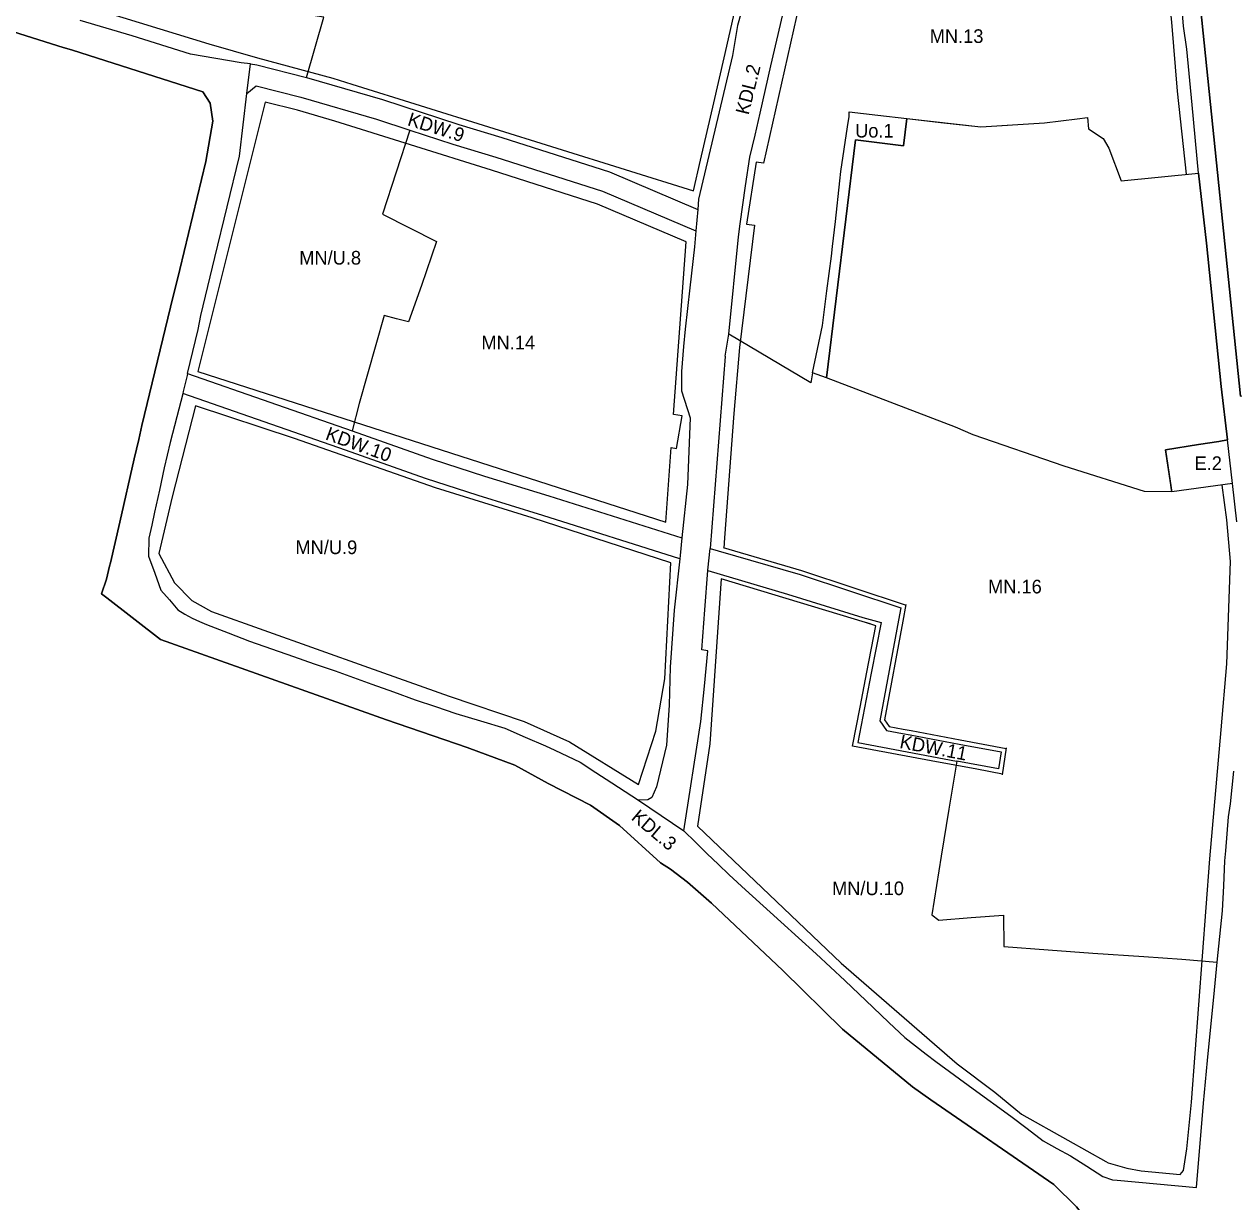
# Model space of a CAD drawing. Extents: x 7423274 to 7424514, y 5542390 to 5544261.
# Drawn here: x 7423885.8 to 7424240.7, y 5543020.6 to 5543366 of the extents above; entities that cross this region are included whole.
import ezdxf

# ---------------------------------------------------------------- set-up
doc = ezdxf.new("R2010")
doc.units = 0
for name, color, linetype in [('granica obszaru objętego planem', 7, 'Continuous'), ('LIN_Granica Planu', 7, 'Continuous'), ('linie rozgraniczające tereny o różnym przeznaczeniu lub różnych zasadach zagospodarowania', 7, 'Continuous'), ('nieprzekraczalna linia zabudowy', 7, 'Continuous'), ('oznaczenia terenów', 7, 'Continuous'), ('tereny dka ktorych obowiazuje_355', 7, 'Continuous')]:
    doc.layers.add(name, color=color, linetype=linetype)

msp = doc.modelspace()

# ---------------------------------------------------------------- linework, layer by layer
at = {"layer": 'granica obszaru objętego planem'}
for p, q in [((7424228.51, 5543394.73), (7424242.62, 5543256.86)), ((7423897.3, 5543359.16), (7423878.95, 5543364.84)), ((7423928.79, 5543282.97), (7423931.47, 5543294.03)), ((7423911.15, 5543208.03), (7423913.87, 5543219.9)), ((7423910, 5543203.23), (7423910.81, 5543207.01)), ((7423910.81, 5543207.01), (7423911.15, 5543208.03)), ((7423908.54, 5543198.88), (7423910, 5543203.23)), ((7423910.05, 5543197.7), (7423908.54, 5543198.88)), ((7423925.77, 5543185.5), (7423910.05, 5543197.7)), ((7423992.07, 5543161.97), (7423925.77, 5543185.5)), ((7424015.82, 5543153.8), (7423992.07, 5543161.97)), ((7424072.5, 5543120.05), (7424060.48, 5543130.94)), ((7424075.4, 5543118.16), (7424072.5, 5543120.05)), ((7424080.4, 5543114.34), (7424075.4, 5543118.16)), ((7424125.89, 5543071.27), (7424108.39, 5543088.46)), ((7424146.47, 5543054.35), (7424125.89, 5543071.27)), ((7424151.82, 5543050.55), (7424146.47, 5543054.35)), ((7424187.91, 5543025.65), (7424151.82, 5543050.55))]:
    msp.add_line(p, q, dxfattribs=at)
for points in [[(7423899.98, 5543358.31), (7423898.37, 5543358.83), (7423897.3, 5543359.16)], [(7423931.47, 5543294.03), (7423939.15, 5543325.65), (7423941.13, 5543337.55), (7423940.41, 5543342.77), (7423938.19, 5543346.07), (7423899.98, 5543358.31)], [(7423919.43, 5543244.17), (7423920.36, 5543248.23), (7423928.79, 5543282.97)], [(7423913.87, 5543219.9), (7423918.12, 5543238.46), (7423919.43, 5543244.17)], [(7424039.53, 5543143.25), (7424029.77, 5543148.7), (7424015.82, 5543153.8)], [(7424060.48, 5543130.94), (7424051.94, 5543136.91), (7424039.53, 5543143.25)], [(7424108.39, 5543088.46), (7424087.42, 5543108.21), (7424080.4, 5543114.34)], [(7424206.38, 5543004.09), (7424194.57, 5543019.14), (7424187.91, 5543025.65)]]:
    msp.add_lwpolyline(points, dxfattribs=at)
at = {"layer": 'LIN_Granica Planu'}
for p, q in [((7424242.62, 5543256.86), (7424228.51, 5543394.73)), ((7423878.95, 5543364.84), (7423897.3, 5543359.16)), ((7423931.47, 5543294.03), (7423928.79, 5543282.97)), ((7423913.87, 5543219.9), (7423911.15, 5543208.03)), ((7423910.81, 5543207.01), (7423910, 5543203.23)), ((7423911.15, 5543208.03), (7423910.81, 5543207.01)), ((7423910, 5543203.23), (7423908.54, 5543198.88)), ((7423908.54, 5543198.88), (7423910.05, 5543197.7)), ((7423910.05, 5543197.7), (7423925.77, 5543185.5)), ((7423925.77, 5543185.5), (7423992.07, 5543161.97)), ((7423992.07, 5543161.97), (7424015.82, 5543153.8)), ((7424060.48, 5543130.94), (7424072.5, 5543120.05)), ((7424072.5, 5543120.05), (7424075.4, 5543118.16)), ((7424075.4, 5543118.16), (7424080.4, 5543114.34)), ((7424108.39, 5543088.46), (7424125.89, 5543071.27)), ((7424125.89, 5543071.27), (7424146.47, 5543054.35)), ((7424146.47, 5543054.35), (7424151.82, 5543050.55)), ((7424151.82, 5543050.55), (7424187.91, 5543025.65))]:
    msp.add_line(p, q, dxfattribs=at)
for points in [[(7423897.3, 5543359.16), (7423898.37, 5543358.83), (7423899.98, 5543358.31)], [(7423899.98, 5543358.31), (7423938.19, 5543346.07), (7423940.41, 5543342.77), (7423941.13, 5543337.55), (7423939.15, 5543325.65), (7423931.47, 5543294.03)], [(7424159.02, 5543247.82), (7424133.19, 5543257.64), (7424121.2, 5543262.2), (7424129.68, 5543332.07), (7424143.76, 5543330.24), (7424144.72, 5543338.31), (7424166.46, 5543335.81), (7424185.12, 5543337.07), (7424194.74, 5543338.24), (7424197.78, 5543338.6), (7424198.07, 5543335.23), (7424202.37, 5543332.42), (7424204.03, 5543329.61), (7424207.65, 5543320), (7424230.35, 5543322.31), (7424232.64, 5543301.72), (7424237.01, 5543259.68), (7424238.8, 5543244.06), (7424236.28, 5543243.6), (7424230.36, 5543242.65), (7424220.63, 5543241.1), (7424222.35, 5543229.95), (7424222.51, 5543228.86), (7424214.52, 5543228.92), (7424190.92, 5543236.36), (7424164.25, 5543245.56), (7424159.02, 5543247.82)], [(7423928.79, 5543282.97), (7423920.36, 5543248.23), (7423919.43, 5543244.17)], [(7423919.43, 5543244.17), (7423918.12, 5543238.46), (7423913.87, 5543219.9)], [(7424015.82, 5543153.8), (7424029.77, 5543148.7), (7424039.53, 5543143.25)], [(7424039.53, 5543143.25), (7424051.94, 5543136.91), (7424060.48, 5543130.94)], [(7424080.4, 5543114.34), (7424087.42, 5543108.21), (7424108.39, 5543088.46)], [(7424187.91, 5543025.65), (7424194.57, 5543019.14), (7424206.38, 5543004.09)]]:
    msp.add_lwpolyline(points, dxfattribs=at)
at = {"layer": 'linie rozgraniczające tereny o różnym przeznaczeniu lub różnych zasadach zagospodarowania'}
msp.add_line((7424130.38, 5543155.27), (7424130.38, 5543155.27), dxfattribs=at)
for points in [[(7424129.39, 5544001.9), (7424129.8, 5543999.91), (7424131.7, 5543990.87), (7424133.97, 5543980.01), (7424148.11, 5543912.49), (7424163.08, 5543838.56), (7424169.46, 5543807.01), (7424175.57, 5543776.81), (7424186.15, 5543728.82), (7424192.74, 5543698.89), (7424202.07, 5543636.25), (7424204.36, 5543612.15), (7424228.15, 5543398.17), (7424228.51, 5543394.73), (7424242.62, 5543256.86), (7424248.04, 5543257.08)], [(7424092.5, 5543275.06), (7424095.41, 5543303.55), (7424095.87, 5543307.37), (7424097.46, 5543318.57), (7424098.68, 5543326.94), (7424100.22, 5543333.4), (7424101.76, 5543339.86), (7424103.33, 5543346.79), (7424104.9, 5543353.71), (7424110.13, 5543376.43), (7424113.79, 5543392.37), (7424117.5, 5543408.62), (7424119.5, 5543417.47), (7424120.06, 5543424.28), (7424124.99, 5543426.4)], [(7424230.35, 5543322.31), (7424228.43, 5543342.33), (7424226.86, 5543358.67), (7424225.94, 5543365.33), (7424224.84, 5543378.57), (7424223.86, 5543388.69), (7424223.21, 5543394.21)], [(7423968.62, 5543350.36), (7423973.77, 5543367.98), (7423958.39, 5543370.37), (7423960.3, 5543381.21), (7423951.96, 5543383.71), (7423943.62, 5543386.21), (7423943.52, 5543385.47), (7423934.92, 5543388.04), (7423926.32, 5543390.6), (7423925.03, 5543386.46), (7423923.73, 5543382.33), (7423914.57, 5543383.96), (7423905.4, 5543385.58)], [(7424096.17, 5543369.34), (7424095.06, 5543365.57), (7424093.62, 5543356.78), (7424089.74, 5543340.3), (7424083.68, 5543314.62), (7424083.42, 5543311.6)], [(7423952.21, 5543354.3), (7423949.45, 5543354.66), (7423934.63, 5543357.19), (7423917.53, 5543362.55), (7423902.29, 5543367.06)], [(7424194.57, 5543019.14), (7424187.91, 5543025.65), (7424151.82, 5543050.55), (7424146.47, 5543054.35), (7424125.89, 5543071.27), (7424108.39, 5543088.46), (7424087.42, 5543108.21), (7424080.4, 5543114.34), (7424075.4, 5543118.16), (7424072.5, 5543120.05), (7424060.48, 5543130.94), (7424051.94, 5543136.91), (7424039.53, 5543143.25), (7424029.77, 5543148.7), (7424015.82, 5543153.8), (7423992.07, 5543161.97), (7423925.77, 5543185.5), (7423910.05, 5543197.7), (7423908.54, 5543198.88), (7423910, 5543203.23), (7423910.81, 5543207.01), (7423911.15, 5543208.03), (7423913.87, 5543219.9), (7423918.12, 5543238.46), (7423919.43, 5543244.17), (7423920.36, 5543248.23), (7423928.79, 5543282.97), (7423931.47, 5543294.03), (7423939.15, 5543325.65), (7423941.13, 5543337.55), (7423940.41, 5543342.77), (7423938.19, 5543346.07), (7423899.98, 5543358.31), (7423898.37, 5543358.83), (7423897.3, 5543359.16), (7423878.95, 5543364.84)], [(7423951.18, 5543345.64), (7423952.21, 5543354.3)], [(7423952.21, 5543354.3), (7423954.1, 5543354.05), (7423968.62, 5543350.36)], [(7423951.18, 5543345.64), (7423953.92, 5543347.91), (7423967.03, 5543344.57), (7423989.14, 5543338.1), (7423998.99, 5543334.88)], [(7423968.62, 5543350.36), (7423990.91, 5543343.83), (7424013.35, 5543336.51), (7424025.92, 5543332.71), (7424057.54, 5543322.61), (7424083.42, 5543311.6)], [(7423933.76, 5543263.48), (7423936.86, 5543276.41), (7423937.65, 5543280.51), (7423941.79, 5543297.58), (7423949, 5543327.23), (7423951.18, 5543345.64)], [(7424117.13, 5543263.74), (7424120.04, 5543277.56), (7424121.33, 5543287.73), (7424122.62, 5543297.9), (7424122.98, 5543300.77), (7424123.83, 5543308.11), (7424125.15, 5543320), (7424125.42, 5543322.72), (7424126.41, 5543329.28), (7424127.39, 5543335.83), (7424127.84, 5543338.85), (7424127.81, 5543340.26), (7424136.27, 5543339.29), (7424144.72, 5543338.31), (7424155.59, 5543337.06), (7424166.46, 5543335.81), (7424175.79, 5543336.44), (7424185.12, 5543337.07), (7424189.93, 5543337.66), (7424194.74, 5543338.24), (7424197.78, 5543338.6), (7424198.07, 5543335.23), (7424202.37, 5543332.42), (7424204.03, 5543329.61), (7424207.65, 5543320), (7424230.35, 5543322.31)], [(7424144.72, 5543338.31), (7424143.76, 5543330.24), (7424129.68, 5543332.07), (7424121.2, 5543262.2)], [(7423998.99, 5543334.88), (7423994.96, 5543322.56), (7423990.91, 5543310.22), (7423998.87, 5543306.21), (7424006.82, 5543302.21), (7424002.34, 5543289.37), (7423998.59, 5543278.63), (7423995.01, 5543279.57), (7423991.43, 5543280.51), (7423988.99, 5543271.92), (7423986.54, 5543263.34), (7423984.09, 5543254.75), (7423982.08, 5543246.68)], [(7423998.99, 5543334.88), (7424011.55, 5543330.78), (7424024.14, 5543326.98), (7424055.45, 5543316.98), (7424082.86, 5543305.31)], [(7424238.8, 5543244.06), (7424237.01, 5543259.68), (7424232.64, 5543301.72), (7424230.35, 5543322.31)], [(7424083.42, 5543311.6), (7424082.86, 5543305.31)], [(7424082.86, 5543305.31), (7424082.46, 5543300.69), (7424081.08, 5543288.61), (7424079.69, 5543276.53), (7424079.26, 5543271.4), (7424078.63, 5543264.1), (7424078.68, 5543258.46), (7424078.68, 5543258.41), (7424081.22, 5543250.56), (7424080.42, 5543230.98), (7424078.79, 5543215.31)], [(7424091.5, 5543268.63), (7424092.5, 5543275.06)], [(7424117.13, 5543263.74), (7424116.6, 5543260.73), (7424092.5, 5543275.06)], [(7424091.49, 5543268.48), (7424087.03, 5543212.2)], [(7424091.5, 5543268.63), (7424091.49, 5543268.48)], [(7423933.76, 5543263.48), (7423933.62, 5543262.88), (7423933.05, 5543260.55), (7423932.48, 5543258.22), (7423932.33, 5543257.62)], [(7423933.76, 5543263.48), (7423982.08, 5543246.68)], [(7424222.51, 5543228.86), (7424214.52, 5543228.92), (7424190.92, 5543236.36), (7424164.25, 5543245.56), (7424159.02, 5543247.82), (7424133.19, 5543257.64), (7424121.2, 5543262.2), (7424117.13, 5543263.74)], [(7423932.32, 5543257.58), (7423930.58, 5543250.76), (7423928.69, 5543243.3), (7423926.88, 5543235.89), (7423925.48, 5543229.35), (7423924.07, 5543222.81), (7423923.23, 5543219.02), (7423922.39, 5543215.23), (7423922.33, 5543209.95), (7423924.14, 5543204.98), (7423925.95, 5543200.01), (7423928.42, 5543197.11), (7423930.9, 5543194.21), (7423933, 5543192.98), (7423935.09, 5543191.74), (7423937.22, 5543190.81), (7423939.35, 5543189.88), (7423945.63, 5543187.46), (7423951.91, 5543185.03), (7423958.39, 5543182.78), (7423964.87, 5543180.52), (7423970.94, 5543178.41), (7423977.01, 5543176.3), (7423982.39, 5543174.37), (7423987.77, 5543172.43), (7423994.15, 5543170.14), (7424000.52, 5543167.85), (7424006.49, 5543165.84), (7424012.45, 5543163.83), (7424019.66, 5543161.67), (7424026.86, 5543159.51), (7424032.82, 5543156.91), (7424038.77, 5543154.31), (7424041.49, 5543153.03), (7424045.19, 5543151.29), (7424048.89, 5543149.55), (7424053.57, 5543146.51), (7424058.24, 5543143.48), (7424062.15, 5543140.95), (7424066.06, 5543138.41)], [(7423932.33, 5543257.62), (7423932.32, 5543257.58)], [(7423932.33, 5543257.62), (7423932.32, 5543257.58)], [(7424078.16, 5543209.21), (7424037.99, 5543221.88), (7424019.03, 5543227.72), (7424003.55, 5543232.72), (7423980.09, 5543241.02), (7423932.33, 5543257.62)], [(7423932.33, 5543257.62), (7423932.33, 5543257.62)], [(7423982.08, 5543246.68), (7424005.47, 5543238.4), (7424020.83, 5543233.45), (7424039.77, 5543227.61), (7424078.79, 5543215.31)], [(7424222.51, 5543228.86), (7424222.35, 5543229.95), (7424222.21, 5543230.86), (7424220.63, 5543241.1), (7424230.36, 5543242.65), (7424236.28, 5543243.6), (7424238.8, 5543244.06)], [(7424240.28, 5543231.21), (7424238.8, 5543244.06)], [(7424240.28, 5543231.21), (7424222.51, 5543228.86)], [(7424241.58, 5543219.98), (7424240.28, 5543231.21)], [(7424078.79, 5543215.31), (7424078.26, 5543210.14), (7424078.16, 5543209.21)], [(7424078.16, 5543209.21), (7424076.52, 5543194.14), (7424075.37, 5543177.44), (7424075.08, 5543166.22), (7424074.26, 5543154.55), (7424071.3, 5543142.34), (7424069.97, 5543139.13), (7424068.77, 5543138.46), (7424066.06, 5543138.41)], [(7424086.41, 5543205.74), (7424086.42, 5543205.89), (7424087.03, 5543212.18), (7424087.03, 5543212.2)], [(7424087.03, 5543212.2), (7424089.38, 5543211.54), (7424113.46, 5543204.54), (7424142.97, 5543194.78), (7424142.29, 5543191.13), (7424136.81, 5543161.69), (7424138.82, 5543158.79), (7424143.5, 5543157.9), (7424145.77, 5543157.56), (7424160.13, 5543154.81), (7424172.4, 5543152.52), (7424171.7, 5543147.57), (7424159.39, 5543149.86)], [(7424079.31, 5543129.38), (7424084.35, 5543161.47), (7424085.37, 5543171.84), (7424086.38, 5543182.22), (7424084.59, 5543182.46), (7424085.5, 5543194.17), (7424086.41, 5543205.74)], [(7424086.41, 5543205.74), (7424109.71, 5543198.84), (7424131.89, 5543191.98), (7424137.21, 5543190.49), (7424134.26, 5543175.67), (7424130.38, 5543155.27), (7424144.86, 5543152.57), (7424159.33, 5543149.87), (7424159.39, 5543149.86)], [(7424159.39, 5543149.86), (7424157.08, 5543135.77), (7424154.81, 5543121.94), (7424153.44, 5543113.37), (7424152.06, 5543104.8), (7424154.11, 5543103.23), (7424163.61, 5543103.95), (7424173.1, 5543104.67), (7424173.18, 5543095.51), (7424186.26, 5543094.54), (7424199.34, 5543093.56), (7424214.31, 5543092.55), (7424225.4, 5543091.77), (7424235.82, 5543090.87)], [(7424235.82, 5543090.87), (7424236.58, 5543098.42), (7424237.33, 5543105.97), (7424237.71, 5543113.26), (7424238.09, 5543120.56), (7424238.32, 5543123.54), (7424239.1, 5543133.52), (7424239.75, 5543137.3), (7424240.23, 5543142.11), (7424240.7, 5543146.91)], [(7424066.06, 5543138.41), (7424072.69, 5543133.9), (7424079.31, 5543129.38)], [(7424079.31, 5543129.38), (7424082.75, 5543126.03), (7424086.18, 5543122.68), (7424089.4, 5543119.59), (7424092.61, 5543116.5), (7424097.43, 5543112.14), (7424099.51, 5543110.26), (7424107.8, 5543102.75), (7424118.18, 5543093.35), (7424126.53, 5543085.46), (7424134.87, 5543077.56), (7424139.5, 5543073.18), (7424144.14, 5543068.8), (7424150.42, 5543063.93), (7424153.23, 5543061.74), (7424164.25, 5543053.74), (7424175.26, 5543045.74), (7424180.03, 5543042.11), (7424184.8, 5543038.47), (7424188.81, 5543036.26), (7424192.82, 5543034.05), (7424197.57, 5543031.05), (7424202.31, 5543028.05), (7424205.05, 5543027.04), (7424206.42, 5543026.96), (7424229.71, 5543024.83), (7424231.81, 5543049.51), (7424232.98, 5543062.03), (7424234.99, 5543082.71), (7424235.82, 5543090.87)]]:
    msp.add_lwpolyline(points, dxfattribs=at)
at = {"layer": 'nieprzekraczalna linia zabudowy'}
for p, q in [((7423976.39, 5543350.12), (7423981.98, 5543348.35)), ((7424226.77, 5543321.95), (7424224.15, 5543346.3)), ((7423956.48, 5543343.13), (7423936.79, 5543264.14)), ((7424076.34, 5543251.53), (7424080.04, 5543302.17)), ((7424074.09, 5543219.89), (7424075.67, 5543241.77)), ((7424091.3, 5543215.29), (7424091.05, 5543212.31)), ((7424073.75, 5543173.94), (7424075.5, 5543208.03)), ((7424134.08, 5543190.07), (7424132.59, 5543190.5)), ((7424173.89, 5543153.74), (7424172.77, 5543145.85)), ((7424224.9, 5543028.64), (7424225.92, 5543029.74))]:
    msp.add_line(p, q, dxfattribs=at)
for points in [[(7424124.14, 5543422.33), (7424118.57, 5543395.65), (7424102.67, 5543325.15), (7424100.54, 5543325.49)], [(7424224.15, 5543346.3), (7424224.15, 5543346.3), (7424222.51, 5543366.56), (7424219.76, 5543393.19)], [(7424082.19, 5543317.08), (7424084.25, 5543326.09), (7424088.18, 5543342.9), (7424091.18, 5543356.07), (7424096.87, 5543381.11)], [(7423905.14, 5543370.81), (7423940.04, 5543360.21), (7423954.31, 5543356.07), (7423976.39, 5543350.12)], [(7423981.98, 5543348.35), (7424082.22, 5543317.12), (7424082.22, 5543317.12)], [(7424080.04, 5543302.17), (7424054.05, 5543313.22), (7424022.95, 5543323.16), (7423999.15, 5543330.62), (7423976.97, 5543337.49), (7423965.98, 5543340.71), (7423956.48, 5543343.13)], [(7424100.54, 5543325.49), (7424097.68, 5543307.34), (7424100.05, 5543306.97)], [(7424100.05, 5543306.97), (7424095.68, 5543271.13)], [(7424095.68, 5543271.13), (7424094.03, 5543251.75), (7424091.31, 5543215.29)], [(7423936.79, 5543264.14), (7424022.41, 5543236.55), (7424074.09, 5543219.89)], [(7423936.09, 5543254.07), (7423929.2, 5543227.3), (7423925.32, 5543210.69), (7423929.9, 5543202.16), (7423934.98, 5543196.99), (7423940.8, 5543193.7), (7423986.84, 5543177.26), (7424010.45, 5543168.86), (7424032.47, 5543161.42), (7424045.76, 5543155.45), (7424066.09, 5543143.02)], [(7424075.5, 5543208.03), (7424034.89, 5543221.21), (7424006.49, 5543229.95), (7423965.17, 5543244.47), (7423936.09, 5543254.07)], [(7424075.67, 5543241.77), (7424077.21, 5543241.53), (7424078.88, 5543251.09), (7424076.34, 5543251.53)], [(7424225.92, 5543029.74), (7424226.91, 5543036.1), (7424228.29, 5543049.78), (7424233.65, 5543121.22), (7424236.99, 5543158.98), (7424238.68, 5543178.34), (7424239.67, 5543208.41), (7424238.66, 5543220.61), (7424237.26, 5543230.81)], [(7424090.89, 5543212.45), (7424113.85, 5543205.78), (7424144.58, 5543195.62)], [(7424090.31, 5543203.29), (7424086.93, 5543154.9), (7424083.37, 5543130.79)], [(7424132.59, 5543190.5), (7424090.31, 5543203.29)], [(7424144.48, 5543195.81), (7424143.57, 5543190.89), (7424138.19, 5543161.99), (7424139.59, 5543159.97), (7424143.72, 5543159.18), (7424145.99, 5543158.84), (7424160.37, 5543156.09), (7424173.94, 5543153.56)], [(7424172.83, 5543146.01), (7424165.28, 5543147.44), (7424151.86, 5543149.94), (7424128.86, 5543154.23), (7424131.04, 5543165.71), (7424132.99, 5543175.92), (7424135.7, 5543189.56), (7424132.59, 5543190.5)], [(7424066.09, 5543143.02), (7424071.14, 5543158.67), (7424073.75, 5543173.94)], [(7424083.37, 5543130.79), (7424125.51, 5543090.59), (7424159.48, 5543061.04), (7424170.62, 5543052.76), (7424178.42, 5543046.28), (7424192.03, 5543038.7), (7424203.12, 5543032.41), (7424203.87, 5543031.99), (7424209.3, 5543030.43), (7424213.46, 5543029.72), (7424224.9, 5543028.64)]]:
    msp.add_lwpolyline(points, dxfattribs=at)
at = {"layer": 'tereny dka ktorych obowiazuje_355'}
msp.add_lwpolyline([(7424159.02, 5543247.82), (7424133.19, 5543257.64), (7424121.2, 5543262.2), (7424129.68, 5543332.07), (7424143.76, 5543330.24), (7424144.72, 5543338.31), (7424166.46, 5543335.81), (7424185.12, 5543337.07), (7424194.74, 5543338.24), (7424197.78, 5543338.6), (7424198.07, 5543335.23), (7424202.37, 5543332.42), (7424204.03, 5543329.61), (7424207.65, 5543320), (7424230.35, 5543322.31), (7424232.64, 5543301.72), (7424237.01, 5543259.68), (7424238.8, 5543244.06), (7424236.28, 5543243.6), (7424230.36, 5543242.65), (7424220.63, 5543241.1), (7424222.35, 5543229.95), (7424222.51, 5543228.86), (7424214.52, 5543228.92), (7424190.92, 5543236.36), (7424164.25, 5543245.56)], close=True, dxfattribs=at)

# ---------------------------------------------------------------- texts
at = {"layer": 'oznaczenia terenów'}
for s, p in [('MN.13', (7424151.48, 5543360.45)), ('Uo.1', (7424129.59, 5543332.72)), ('MN/U.8', (7423966.52, 5543295.46)), ('MN.14', (7424019.95, 5543270.57)), ('E.2', (7424229.16, 5543235.22)), ('MN/U.9', (7423965.41, 5543210.55)), ('MN.16', (7424168.59, 5543199.03)), ('MN/U.10', (7424122.81, 5543110.54))]:
    msp.add_text(s, height=4, dxfattribs=at).set_placement(p)
for s, rotation, p in [('KDL.2', 76.1043, (7424098.33, 5543339.16)), ('KDW.9', 342.696, (7423998.02, 5543336.37)), ('KDW.10', 340.1085, (7423973.94, 5543244.26)), ('KDW.11', 349.1962, (7424142.45, 5543153.71)), ('KDL.3', 319.8974, (7424063.67, 5543132.92))]:
    msp.add_text(s, height=4, rotation=rotation, dxfattribs=at).set_placement(p)

doc.saveas('drawing.dxf')
